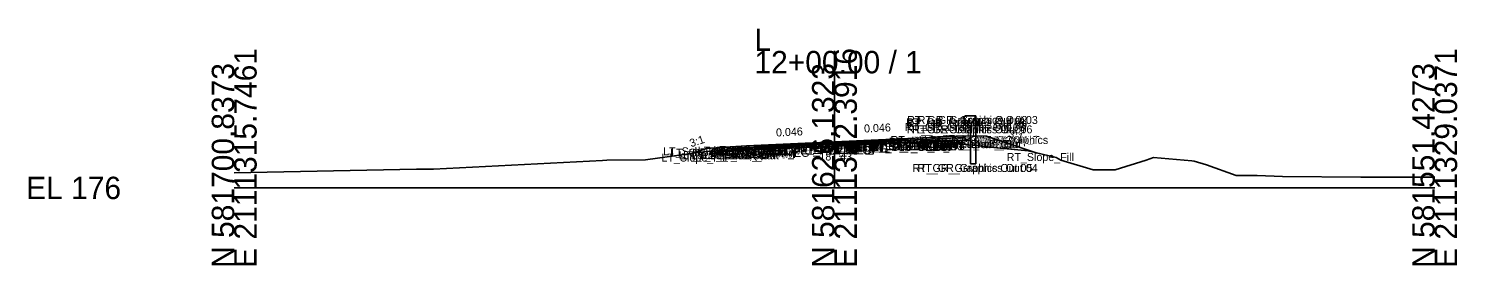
# Model space of a CAD drawing. Extents: x -26 to 3453, y -333 to 9539.
# Drawn here: x -25.7 to 152.8, y 1490.3 to 1519.9 of the extents above; entities that cross this region are included whole.
import ezdxf

# ---------------------------------------------------------------- set-up
doc = ezdxf.new("R2010")
doc.units = 0
for name, color, linetype in [('Default', 7, 'Continuous'), ('Exist Cross Section Cell', 7, 'Continuous'), ('Exist XS Center Line Elevation Label', 7, 'Continuous'), ('Exist XS Ground Line', 7, 'Continuous'), ('Prop CMT Guardrail Graphics', 7, 'Continuous'), ('Prop CMT Pvmt Course 1', 7, 'Continuous'), ('Prop CMT Pvmt Course 1 Wedge', 7, 'Continuous'), ('Prop CMT Pvmt Course 2', 7, 'Continuous'), ('Prop CMT Pvmt Course 2 Wedge', 7, 'Continuous'), ('Prop CMT Pvmt Course 3', 7, 'Continuous'), ('Prop CMT Pvmt Surface', 7, 'Continuous'), ('Prop CMT Pvmt Surface Shoulder', 7, 'Continuous'), ('Prop CMT Pvmt Wedge Surface 1', 7, 'Continuous'), ('Prop CMT Pvmt Wedge Surface 2', 7, 'Continuous'), ('Prop CMT Pvmt Wedge Surface 3', 7, 'Continuous'), ('Prop CMT Shld Paved Course 1', 7, 'Continuous'), ('Prop CMT Shld Paved Course 2', 7, 'Continuous'), ('Prop CMT Shld Paved Course 3', 7, 'Continuous'), ('Prop CMT Slope Grass', 7, 'Continuous'), ('Prop CMT Subgrade Earthwork', 7, 'Continuous'), ('Prop XS SE Text', 7, 'Continuous'), ('Prop XS Side Slope Text', 7, 'Continuous'), ('Scratch_Level_0', 7, 'Continuous')]:
    doc.layers.add(name, color=color, linetype=linetype)

msp = doc.modelspace()

# ---------------------------------------------------------------- linework, layer by layer
at = {"layer": 'Exist Cross Section Cell'}
for p, q in [((75, 1500), (75, 1517.12)), ((0, 1500), (75, 1500)), ((75, 1500), (150, 1500))]:
    msp.add_line(p, q, dxfattribs=at)
at = {"layer": 'Exist XS Ground Line'}
for p, q in [((65.01, 1504.88), (73.51, 1505.37)), ((73.51, 1505.37), (74.35, 1505.41)), ((74.35, 1505.41), (75.23, 1505.44)), ((75.23, 1505.44), (84.26, 1505.71)), ((84.26, 1505.71), (84.88, 1505.7)), ((84.88, 1505.7), (86.53, 1505.65)), ((86.53, 1505.65), (90.27, 1505.57)), ((90.27, 1505.57), (95.29, 1505.01)), ((24.89, 1502.36), (46.03, 1503.42)), ((46.03, 1503.42), (46.57, 1503.47)), ((46.57, 1503.47), (51.4, 1503.51)), ((51.4, 1503.51), (58.94, 1504.55)), ((58.94, 1504.55), (65.01, 1504.88)), ((95.29, 1505.01), (99.22, 1504.62)), ((99.22, 1504.62), (102.7, 1503.79)), ((102.7, 1503.79), (103.27, 1503.46)), ((103.27, 1503.46), (107.31, 1502.26)), ((110.08, 1502.24), (113.93, 1503.45)), ((113.93, 1503.45), (114.86, 1503.79)), ((114.86, 1503.79), (119.65, 1503.39)), ((119.65, 1503.39), (119.96, 1503.36)), ((119.96, 1503.36), (121.49, 1502.9)), ((0, 1501.9), (22.77, 1502.33)), ((22.77, 1502.33), (24.22, 1502.33)), ((24.22, 1502.33), (24.89, 1502.36)), ((107.31, 1502.26), (108.06, 1502.25)), ((108.06, 1502.25), (110.08, 1502.24)), ((121.49, 1502.9), (125.21, 1501.54)), ((125.21, 1501.54), (127.81, 1501.54)), ((127.81, 1501.54), (130.97, 1501.42)), ((130.97, 1501.42), (140.78, 1501.35)), ((140.78, 1501.35), (150, 1501.34))]:
    msp.add_line(p, q, dxfattribs=at)
at = {"layer": 'Prop CMT Guardrail Graphics'}
for points in [[(92.67, 1508.99), (91.34, 1508.99), (91.07, 1508.7)], [(91.07, 1508.7), (91.34, 1508.41)], [(92.67, 1502.99), (92.67, 1508.99)], [(91.34, 1508.41), (91.07, 1508.11)], [(91.07, 1508.11), (91.34, 1507.82), (92.01, 1507.82)], [(92.01, 1507.82), (92.01, 1502.99)], [(92.01, 1502.99), (92.67, 1502.99)]]:
    msp.add_lwpolyline(points, dxfattribs=at)
at = {"layer": 'Prop CMT Pvmt Course 1'}
for points in [[(75, 1505.75), (64, 1505.24)], [(64, 1505.24), (64, 1505.04)], [(64, 1505.04), (65.01, 1505.08)], [(65.01, 1505.17), (75, 1505.62)], [(65.01, 1505.08), (65.01, 1505.17)], [(75, 1505.75), (86, 1506.26)], [(84.26, 1506.05), (75, 1505.62)], [(75, 1505.54), (75, 1505.75)], [(75, 1505.54), (75, 1505.75)], [(75, 1505.62), (75, 1505.54), (75, 1505.54)], [(75, 1505.62), (75, 1505.54), (75, 1505.54)], [(86, 1506.05), (84.26, 1505.97)], [(84.26, 1505.97), (84.26, 1506.05)], [(86, 1506.26), (86, 1506.05)]]:
    msp.add_lwpolyline(points, dxfattribs=at)
at = {"layer": 'Prop CMT Pvmt Course 1 Wedge'}
for points in [[(65.01, 1505.17), (65.01, 1505.17), (73.51, 1505.56), (74.35, 1505.59), (75, 1505.62)], [(75, 1505.5), (74.35, 1505.47), (73.51, 1505.43), (65.01, 1505.04), (65.01, 1505.04)], [(65.01, 1505.04), (65.01, 1505.17)], [(75, 1505.62), (75.23, 1505.64), (84.26, 1506.05), (84.26, 1506.05)], [(84.26, 1505.93), (84.26, 1505.93), (75.23, 1505.51), (75, 1505.5)], [(75, 1505.62), (75, 1505.5)], [(75, 1505.5), (75, 1505.62)], [(84.26, 1506.05), (84.26, 1505.93)]]:
    msp.add_lwpolyline(points, dxfattribs=at)
at = {"layer": 'Prop CMT Pvmt Course 2'}
for points in [[(65.01, 1505.08), (64, 1505.04)], [(64, 1505.04), (64, 1504.7)], [(65.01, 1504.75), (65.01, 1505.08)], [(84.26, 1505.97), (86, 1506.05)], [(84.26, 1505.63), (84.26, 1505.97)], [(86, 1505.71), (84.26, 1505.63)], [(86, 1506.05), (86, 1505.71)], [(64, 1504.7), (65.01, 1504.75)]]:
    msp.add_lwpolyline(points, dxfattribs=at)
at = {"layer": 'Prop CMT Pvmt Course 2 Wedge'}
for points in [[(65.01, 1505.08), (65.01, 1505.08), (73.51, 1505.47), (74.35, 1505.51), (75, 1505.54)], [(75, 1505.43), (74.35, 1505.41), (73.51, 1505.37), (65.01, 1504.88), (65.01, 1504.88)], [(65.01, 1504.88), (65.01, 1505.08)], [(75, 1505.54), (75.23, 1505.55), (84.26, 1505.97), (84.26, 1505.97)], [(84.26, 1505.71), (84.26, 1505.71), (75.23, 1505.44), (75, 1505.43)], [(75, 1505.54), (75, 1505.43)], [(75, 1505.43), (75, 1505.54)], [(84.26, 1505.97), (84.26, 1505.71)]]:
    msp.add_lwpolyline(points, dxfattribs=at)
at = {"layer": 'Prop CMT Pvmt Course 3'}
for points in [[(84.26, 1505.63), (86, 1505.71)], [(86, 1505.71), (84.26, 1505.63)], [(84.26, 1505.63), (84.26, 1505.63)], [(86, 1505.71), (86, 1505.71)], [(65.01, 1504.75), (64, 1504.7)], [(64, 1504.7), (65.01, 1504.75)], [(64, 1504.7), (64, 1504.7)], [(65.01, 1504.75), (65.01, 1504.75)]]:
    msp.add_lwpolyline(points, dxfattribs=at)
at = {"layer": 'Prop CMT Pvmt Surface'}
for points in [[(75, 1505.75), (64, 1505.24)], [(75, 1505.75), (86, 1506.26)]]:
    msp.add_lwpolyline(points, dxfattribs=at)
at = {"layer": 'Prop CMT Pvmt Surface Shoulder'}
for points in [[(64, 1505.24), (62, 1505.15)], [(86, 1506.26), (91.06, 1506.49)]]:
    msp.add_lwpolyline(points, dxfattribs=at)
at = {"layer": 'Prop CMT Pvmt Wedge Surface 1'}
for points in [[(64, 1505.04), (64, 1505.24)], [(65.01, 1505.08), (64, 1505.04)], [(75, 1505.62), (65.01, 1505.17)], [(65.01, 1505.17), (65.01, 1505.08)], [(75, 1505.62), (84.26, 1506.05)], [(84.26, 1506.05), (84.26, 1505.97)], [(84.26, 1505.97), (86, 1506.05)], [(86, 1506.05), (86, 1506.26)]]:
    msp.add_lwpolyline(points, dxfattribs=at)
at = {"layer": 'Prop CMT Pvmt Wedge Surface 2'}
for points in [[(75, 1505.54), (64, 1505.04)], [(64, 1505.04), (64, 1505.24)], [(75, 1505.54), (86, 1506.05)], [(86, 1506.05), (86, 1506.26)]]:
    msp.add_lwpolyline(points, dxfattribs=at)
at = {"layer": 'Prop CMT Pvmt Wedge Surface 3'}
for points in [[(64, 1504.7), (64, 1505.24)], [(75, 1505.21), (64, 1504.7)], [(75, 1505.21), (86, 1505.71)], [(86, 1505.71), (86, 1506.26)]]:
    msp.add_lwpolyline(points, dxfattribs=at)
at = {"layer": 'Prop CMT Shld Paved Course 1'}
for points in [[(64, 1505.24), (62, 1505.15), (61.78, 1504.93)], [(61.78, 1504.93), (64, 1505.04)], [(64, 1505.04), (64, 1505.24)], [(86, 1506.26), (91.06, 1506.49), (91.26, 1506.29)], [(91.26, 1506.29), (86, 1506.05)], [(86, 1506.05), (86, 1506.26)]]:
    msp.add_lwpolyline(points, dxfattribs=at)
at = {"layer": 'Prop CMT Shld Paved Course 2'}
for points in [[(64, 1505.04), (61.78, 1504.93), (61.43, 1504.58)], [(64, 1504.7), (64, 1505.04)], [(86, 1506.05), (91.26, 1506.29), (91.58, 1505.97)], [(86, 1505.71), (86, 1506.05)], [(91.58, 1505.97), (86, 1505.71)], [(61.43, 1504.58), (64, 1504.7)]]:
    msp.add_lwpolyline(points, dxfattribs=at)
at = {"layer": 'Prop CMT Shld Paved Course 3'}
for points in [[(86, 1505.71), (91.58, 1505.97)], [(91.58, 1505.97), (86, 1505.71)], [(86, 1505.71), (86, 1505.71)], [(91.58, 1505.97), (91.58, 1505.97), (91.58, 1505.97)], [(64, 1504.7), (61.43, 1504.58)], [(61.43, 1504.58), (64, 1504.7)], [(61.43, 1504.58), (61.43, 1504.58), (61.43, 1504.58)], [(64, 1504.7), (64, 1504.7)]]:
    msp.add_lwpolyline(points, dxfattribs=at)
at = {"layer": 'Prop CMT Slope Grass'}
for points in [[(62, 1505.15), (59, 1504.91), (57.16, 1504.3)], [(91.06, 1506.49), (91.07, 1506.49)], [(91.07, 1506.49), (94, 1506.45)], [(94, 1506.45), (100.34, 1504.36)]]:
    msp.add_lwpolyline(points, dxfattribs=at)
at = {"layer": 'Prop CMT Subgrade Earthwork'}
for points in [[(61.43, 1504.58), (60.95, 1505.07)], [(84.26, 1505.63), (86, 1505.71)], [(84.26, 1505.63), (84.26, 1505.71)], [(86, 1505.71), (91.58, 1505.97)], [(91.58, 1505.97), (92.08, 1506.47)], [(64, 1504.7), (61.43, 1504.58)], [(65.01, 1504.75), (64, 1504.7)], [(65.01, 1504.75), (65.01, 1504.88)]]:
    msp.add_lwpolyline(points, dxfattribs=at)

# ---------------------------------------------------------------- texts
at = {"layer": 'Default'}
msp.add_text('-', height=0.0001, dxfattribs=at).set_placement((0, 1500))
at = {"layer": 'Exist Cross Section Cell'}
for s, p in [('L', (65, 1517.12)), ('12+00.00 / 1', (65, 1514.32)), ('EL 176', (-26, 1498.6))]:
    msp.add_text(s, height=2.8, dxfattribs=at).set_placement(p)
for s, p in [('E 2111315.7461', (2.8, 1490)), ('E 2111322.3916', (77.8, 1490)), ('E 2111329.0371', (152.8, 1490)), ('N 581700.8373', (0, 1490)), ('N 581626.1323', (75, 1490)), ('N 581551.4273', (150, 1490))]:
    msp.add_text(s, height=2.8, rotation=90, dxfattribs=at).set_placement(p)
at = {"layer": 'Exist XS Center Line Elevation Label'}
msp.add_text('181.43', height=1, dxfattribs=at).set_placement((73.12, 1503.43))
at = {"layer": 'Prop XS SE Text'}
for p in [(67.72, 1506.42), (78.72, 1506.92)]:
    msp.add_text('0.046', height=1, rotation=2.6337, dxfattribs=at).set_placement(p)
at = {"layer": 'Prop XS Side Slope Text'}
for rotation, p in [(341.7371, (96.65, 1506.36)), (18.2629, (57.09, 1505.07))]:
    msp.add_text('3:1', height=1, rotation=rotation, dxfattribs=at).set_placement(p)
at = {"layer": 'Scratch_Level_0'}
for s, p in [('RT_GR_Graphics Out 01', (83.96, 1507.7)), ('RT_GR_Graphics Out 02', (84.08, 1507.99)), ('RT_GR_Graphics Out 03', (85.4, 1507.99)), ('RT_GR_Graphics Out 08', (83.78, 1507.11)), ('RT_GR_Graphics Out 07', (84.04, 1506.82)), ('RT_GR_Graphics Out 09', (84.06, 1507.41)), ('RT_GR_Graphics Out 06', (84.72, 1506.82)), ('LT_Sub_Trench_Out_DLT', (53.6, 1504.07)), ('LT_PS1_OEOP', (57.91, 1504.15)), ('LT_PV2_OEOT', (59.75, 1504.04)), ('LT_PV1_OEOT', (59.87, 1504.24)), ('LT_PV2_OEEOP', (60.4, 1504.08)), ('LT_PV1_OEEOP', (60.52, 1504.17)), ('RT_PV_IEEOP_EG', (69.92, 1504.43)), ('LT_PV_IEEOP_EG', (69.98, 1504.43)), ('RT_PV2_IEEOP', (70.71, 1504.54)), ('RT_PV3_IEEOP', (70.71, 1504.21)), ('LT_PV2_IEEOP', (70.77, 1504.54)), ('LT_PV3_IEEOP', (70.77, 1504.21)), ('RT_PV1_IEEOP', (70.83, 1504.62)), ('LT_PV1_IEEOP', (70.89, 1504.62)), ('PV2_PGL', (72.35, 1504.54)), ('PV1_PGL', (72.47, 1504.75)), ('RT_PV_OEEOP_EG', (78.8, 1504.71)), ('RT_Sub Tie Out', (79.36, 1504.71)), ('RT_PV2_OEEOP', (79.6, 1504.97)), ('RT_PV3_OEEOP', (79.6, 1504.63)), ('RT_Sub_OEEOP', (79.62, 1504.63)), ('RT_PV1_OEEOP', (79.72, 1505.05)), ('RT_PV2_OEOT', (81.69, 1505.05)), ('RT_PV3_OEOT', (81.69, 1504.71)), ('RT_Sub_OEOT', (81.71, 1504.71)), ('RT_PV1_OEOT', (81.81, 1505.26)), ('RT_GS_OS_GR_Face_Graphics', (82.01, 1505.49)), ('RT_Sub_Trench_Out_DLT', (84.67, 1505.47)), ('RT_Sub_Trench_Out', (85.63, 1504.97)), ('RT_PS3_Shelf_Out', (86.17, 1504.97)), ('RT_PS1_OEOP', (86.91, 1505.49)), ('RT_PS2_OEOP', (86.99, 1505.29)), ('RT_PS3_OEOP', (87.3, 1504.97)), ('RT_GS_OS_CTL', (89.4, 1505.45)), ('LT_Slope_Fill', (53.39, 1503.3)), ('LT_GS_OS_CTL', (54.46, 1503.91)), ('LT_Sub_Trench_Out', (55.54, 1503.58)), ('LT_PS3_Shelf_Out', (56.09, 1503.58)), ('LT_PS3_OEOP', (57.22, 1503.58)), ('LT_PS2_OEOP', (57.57, 1503.93)), ('LT_PV_OEEOP_EG', (59.61, 1503.88)), ('LT_PV3_OEOT', (59.75, 1503.7)), ('LT_Sub_OEOT', (59.77, 1503.7)), ('LT_Sub Tie Out', (60.16, 1503.88)), ('LT_PV3_OEEOP', (60.4, 1503.75)), ('LT_Sub_OEEOP', (60.42, 1503.75)), ('RT_Slope_Fill', (96.52, 1503.36)), ('RT_GR_Graphics Out 05', (84.73, 1501.99)), ('RT_GR_Graphics Out 04', (85.38, 1501.99))]:
    msp.add_text(s, height=1, dxfattribs=at).set_placement(p)

doc.saveas('drawing.dxf')
